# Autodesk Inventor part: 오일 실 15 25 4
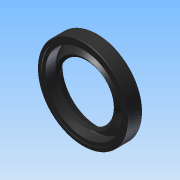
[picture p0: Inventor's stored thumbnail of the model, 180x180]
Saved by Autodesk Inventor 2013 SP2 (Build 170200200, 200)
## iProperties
Created: 2025-10
Part Number: 오일 실 15 25 4
Material: Generic
Document SubType Name: Modeling
Designer: 601
Density: 1 g/cm^3
Author: 601
변환 표준: STEP AP214IS
전처리기: Build: 200, Release: 2013 SP2 Update 6 - Date: Thu 07/17/2014
전송 단위: 밀리미터
불확실성: 0.01
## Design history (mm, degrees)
node "오일 실 15 25 41"
body "Solid1"
node "기준1"
